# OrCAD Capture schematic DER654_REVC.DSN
size Custom; title: DER-654 RevA
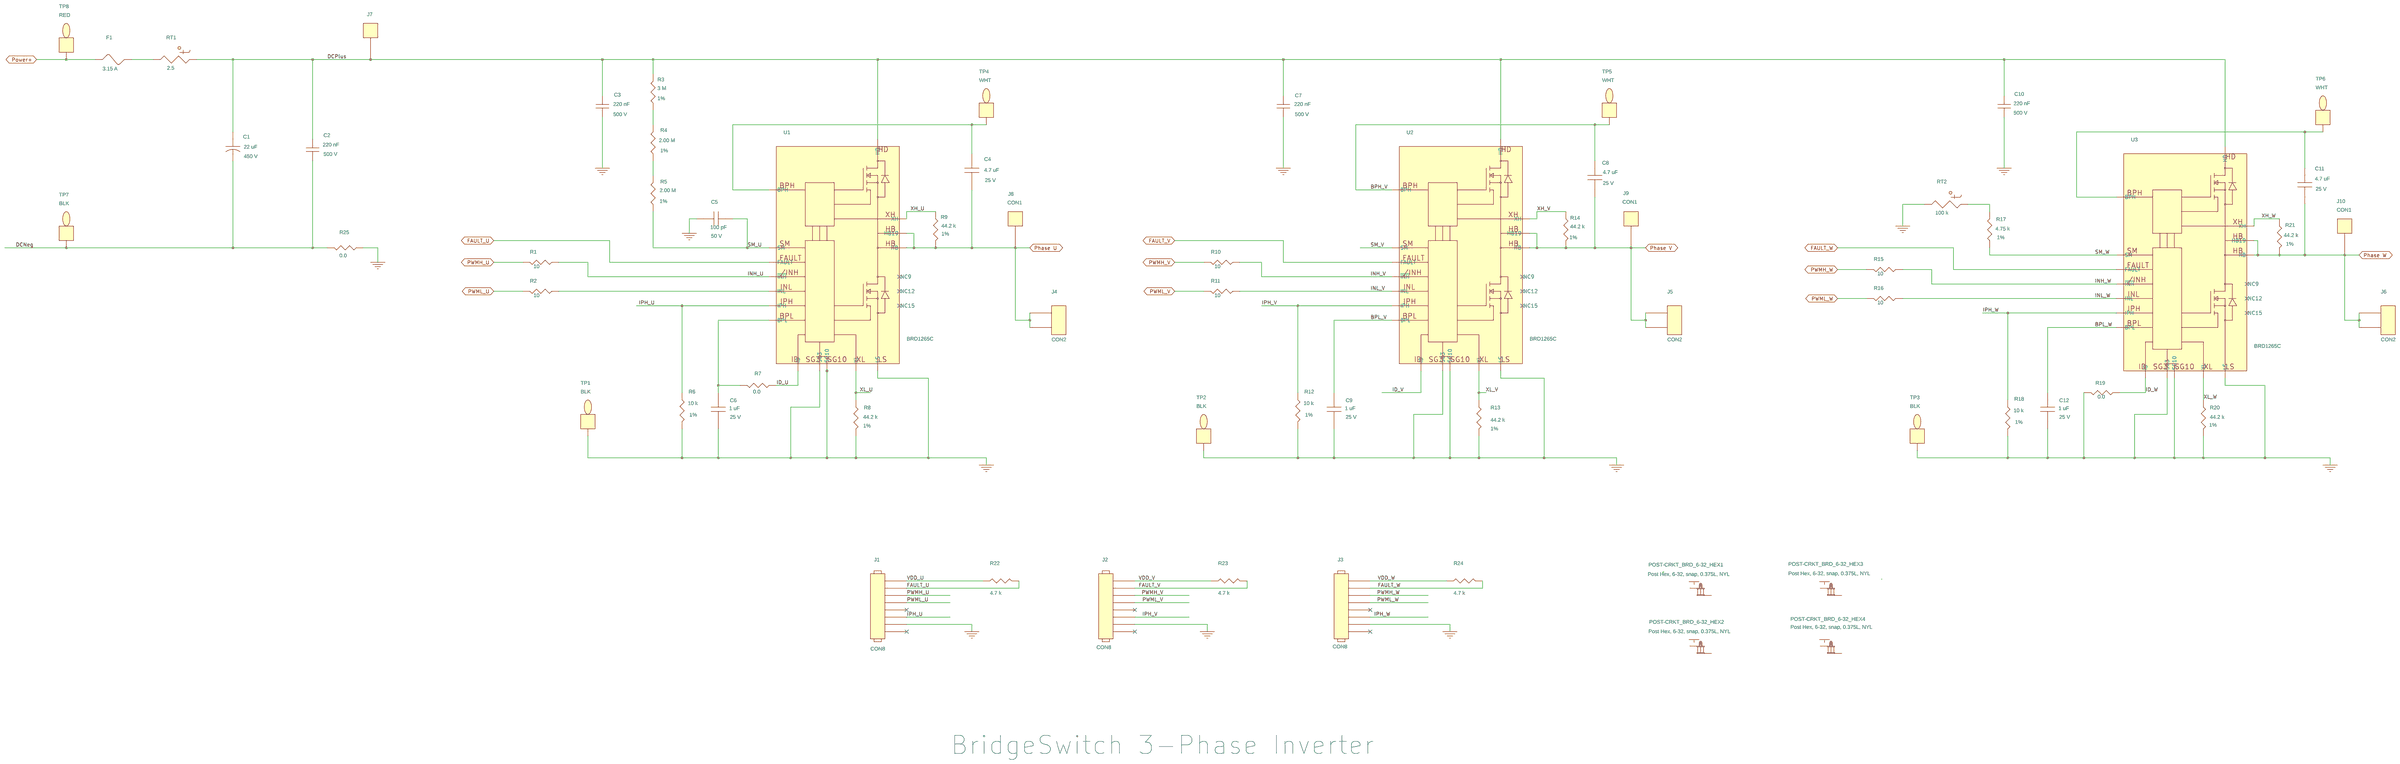
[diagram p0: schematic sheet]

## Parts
C1  22 uF  [pipolcapclyd630ls300040]
C2  220 nF  [pismc1812]
C3  220 nF  [pismc1812]
C4  4.7 uF  [pismc1206]
C5  100 pF  [pismc0603]
C6  1 uF  [pismc0603]
C7  220 nF  [pismc1812]
C8  4.7 uF  [pismc1206]
C9  1 uF  [pismc0603]
C10  220 nF  [pismc1812]
C11  4.7 uF  [pismc1206]
C12  1 uF  [pismc0603]
F1  3.15 A  [pi_tr5_submin_fuse]
J1  CON8  [HDR1X8]
J2  CON8  [HDR1X8]
J3  CON8  [HDR1X8]
J4  CON2  [pi_conn_qc_tab_2pin_ls200]
J5  CON2  [pi_conn_qc_tab_2pin_ls200]
J6  CON2  [pi_conn_qc_tab_2pin_ls200]
J7  CON1  [pi_Keystone1514-2_post]
J8  CON1  [pi_Keystone1514-2_post]
J9  CON1  [pi_Keystone1514-2_post]
J10  CON1  [pi_Keystone1514-2_post]
POST-CRKT_BRD_6-32_HEX1  Post Hex, 6-32, snap, 0.375L, NYL  [pimtgholed156]
POST-CRKT_BRD_6-32_HEX2  Post Hex, 6-32, snap, 0.375L, NYL  [pimtgholed156]
POST-CRKT_BRD_6-32_HEX3  Post Hex, 6-32, snap, 0.375L, NYL  [pimtgholed156]
POST-CRKT_BRD_6-32_HEX4  Post Hex, 6-32, snap, 0.375L, NYL  [pimtgholed156]
R1  10  [pismr0603]
R2  10  [pismr0603]
R3  3 M  [pismr1206]
R4  2.00 M  [pismr1206]
R5  2.00 M  [pismr1206]
R6  10 k  [pismr0603]
R7  0.0  [pismr0603]
R8  44.2 k  [pismr0603]
R9  44.2 k  [pismr0805]
R10  10  [pismr0603]
R11  10  [pismr0603]
R12  10 k  [pismr0603]
R13  44.2 k  [pismr0603]
R14  44.2 k  [pismr0805]
R15  10  [pismr0603]
R16  10  [pismr0603]
R17  4.75 k  [pismr0805]
R18  10 k  [pismr0603]
R19  0.0  [pismr0603]
R20  44.2 k  [pismr0603]
R21  44.2 k  [pismr0805]
R22  4.7 k  [pismr0603]
R23  4.7 k  [pismr0603]
R24  4.7 k  [pismr0603]
R25  0.0  [pismr1206]
RT1  2.5  [pi_rad180x395ls235d031]
RT2  100 k  [pi_rad_118x118_ls100d025]
TP1  BLK  [pitpkeystone125x125]
TP2  BLK  [pitpkeystone125x125]
TP3  BLK  [pitpkeystone125x125]
TP4  WHT  [pitpkeystone100x100]
TP5  WHT  [pitpkeystone100x100]
TP6  WHT  [pitpkeystone100x100]
TP7  BLK  [pitpkeystone125x125]
TP8  RED  [pitpkeystone125x125]
U1  BRD1265C  [pi_ic_insop_24C]
U2  BRD1265C  [pi_ic_insop_24C]
U3  BRD1265C  [pi_ic_insop_24C]

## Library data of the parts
C1 = CAP_POL: Disp_Voltage: 450 V; Part Number: 20-09039-00; ROOM: 1; Voltage: 160 V
C2 C3 C7 C10 = CAP_NP_v3: Disp_Voltage: 500 V; Part Number: 20-08903-00; ROOM: 1; Voltage: 500 V
C4 C8 C11 = CAP_NP: Disp_Voltage: 25 V; Part Number: 20-09136-00; Voltage: 25 V
C5 = CAP_NP: Disp_Voltage: 50 V; Part Number: 20-01025-00; ROOM: 4; Voltage: 50 V
C6 C9 C12 = CAP_NP: ALT_SYMBOLS: pismc0603_1; Disp_Voltage: 25 V; FPLIST: pismc0603,pismc0603_1; Part Number: 20-09147-00; ROOM: 4; Voltage: 25 V
F1 = FUSE: Part Number: 40-00001-00; ROOM: 1
J1-J3 = HEADER_8: Part Number: 35-00342-00; ROOM: 2
J4-J6 = CON2: Part Number: 35-00281-00
J7 = TERM_1Pin: Part Number: 35-00366-00; ROOM: 1
J8 J10 = TERM_1Pin: Part Number: 35-00366-00; ROOM: 4
J9 = TERM_1Pin: Part Number: 35-00366-00
POST-CRKT_BRD_6-32_HEX1-POST-CRKT_BRD_6-32_HEX4 = POST_CRKT_BRD_6-32_HEX: Part Number: 76-00003-00
R1 R2 R10 R11 R15 R16 = R: Part Number: 05-01640-00
R3 = R: Disp_Tol: 1%; Part Number: 05-05562-00; ROOM: 4
R4 R5 = R: Disp_Tol: 1%; Part Number: 05-03156-00; ROOM: 4
R6 R12 R18 = R: Disp_Tol: 1%; Part Number: 05-03182-00
R7 = R: Part Number: 05-03158-00; ROOM: 4
R8 R13 R20 = R: Disp_Tol: 1%; Part Number: 05-03246-00
R9 R14 R21 = R: Disp_Tol: 1%; Part Number: 05-00746-00
R17 = R: Disp_Tol: 1%; Part Number: 05-03371-00
R19 = R: Part Number: 05-03158-00
R22-R24 = R: Part Number: 05-01704-00
R25 = R: Part Number: 05-03160-00
RT1 = THERMISTOR: ALT_SYMBOLS: pirad550x410ls300040_h; FPLIST: pi_rad180x395ls235d031,pirad550x410ls300040_h; Part Number: 90-00053-00
RT2 = THERMISTOR: Part Number: 91-00011-00
TP1 TP7 = TESTPOINT: Part Number: 35-00042-00; ROOM: 4
TP2 TP3 = TESTPOINT: Part Number: 35-00042-00
TP4-TP6 = TESTPOINT: Part Number: 35-00081-00
TP8 = TESTPOINT: Part Number: 35-00043-00; ROOM: 4
U1-U3 = BridgeSwitch: Part Number: 10-01003-00

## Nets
GND: C3.2 C5.2 C6.2 C7.2 C9.2 C10.2 C12.2 J1.7 J2.7 J3.7 R6.2 R8.2 R12.2 R13.2 R18.2 R19.1 R20.2 R25.1 RT2.1 TP1.1 TP2.1 TP3.1 U1.3(SG3) U1.10(SG10) U1.24(LS) U2.3(SG3) U2.10(SG10) U2.24(LS) U3.3(SG3) U3.10(SG10) U3.24(LS)
VDD_U: J1.1 R22.1
VDD_V: J2.1 R23.1
VDD_W: J3.1 R24.1
BPH_V: C8.1 TP5.1 U2.14(BPH)
BPL_V: C9.1 U2.4(BPL)
BPL_W: C12.1 U3.4(BPL)
DCNeg: C1.2 C2.2 R25.2 TP7.1
DCPlus: C1.1 C2.1 C3.1 C7.1 C10.1 J7.1 R3.1 RT1.2 U1.25(HD) U2.25(HD) U3.25(HD)
FAULT_U: J1.2 R22.2 U1.7(FAULT)
FAULT_V: J2.2 R23.2 U2.7(FAULT)
FAULT_W: J3.2 R24.2 U3.7(FAULT)
ID_U: R7.2 U1.11(ID)
ID_V: U2.11(ID)
ID_W: R19.2 U3.11(ID)
INH_U: R1.2 U1.6(~{INH})
INH_V: R10.2 U2.6(~{INH})
INH_W: R15.2 U3.6(~{INH})
INL_V: R11.2 U2.5(INL)
INL_W: R16.2 U3.5(INL)
IPH_U: J1.6 R6.1 U1.2(IPH)
IPH_V: J2.6 R12.1 U2.2(IPH)
IPH_W: J3.6 R18.1 U3.2(IPH)
Phase U: C4.2 J4.1 J4.2 J8.1 R9.2 U1.16(HB) U1.19(HB19)
Phase V: C8.2 J5.1 J5.2 J9.1 R14.2 U2.16(HB) U2.19(HB19)
Phase W: C11.2 J6.1 J6.2 J10.1 R21.2 U3.16(HB) U3.19(HB19)
Power+: F1.1 TP8.1
PWMH_U: J1.3 R1.1
PWMH_V: J2.3 R10.1
PWMH_W: J3.3 R15.1
PWML_U: J1.4 R2.1
PWML_V: J2.4 R11.1
PWML_W: J3.4 R16.1
SM_U: C5.1 R5.1 U1.8(SM)
SM_V: U2.8(SM)
SM_W: R17.1 U3.8(SM)
XH_U: R9.1 U1.13(XH)
XH_V: R14.1 U2.13(XH)
XH_W: R21.1 U3.13(XH)
XL_U: R8.1 U1.1(XL)
XL_V: R13.1 U2.1(XL)
XL_W: R20.1 U3.1(XL)
N17053801: R3.2 R4.2
N17053803: R4.1 R5.2
N17056296: C4.1 TP4.1 U1.14(BPH)
N17067195: C11.1 TP6.1 U3.14(BPH)
N17109437: R17.2 RT2.2
N17176096: F1.2 RT1.1
N17218688: R2.2 U1.5(INL)
N17224134: C6.1 R7.1 U1.4(BPL)

Not connected (* = marked no-connect by the designer): J1 5* 8*; J2 5* 8*; J3 5* 8*; POST-CRKT_BRD_6-32_HEX1 1; POST-CRKT_BRD_6-32_HEX2 1; POST-CRKT_BRD_6-32_HEX3 1; POST-CRKT_BRD_6-32_HEX4 1; U1 9(NC9)* 12(NC12)* 15(NC15)*; U2 9(NC9)* 12(NC12)* 15(NC15)*; U3 9(NC9)* 12(NC12)* 15(NC15)*

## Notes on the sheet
- BridgeSwitch 3-Phase Inverter
